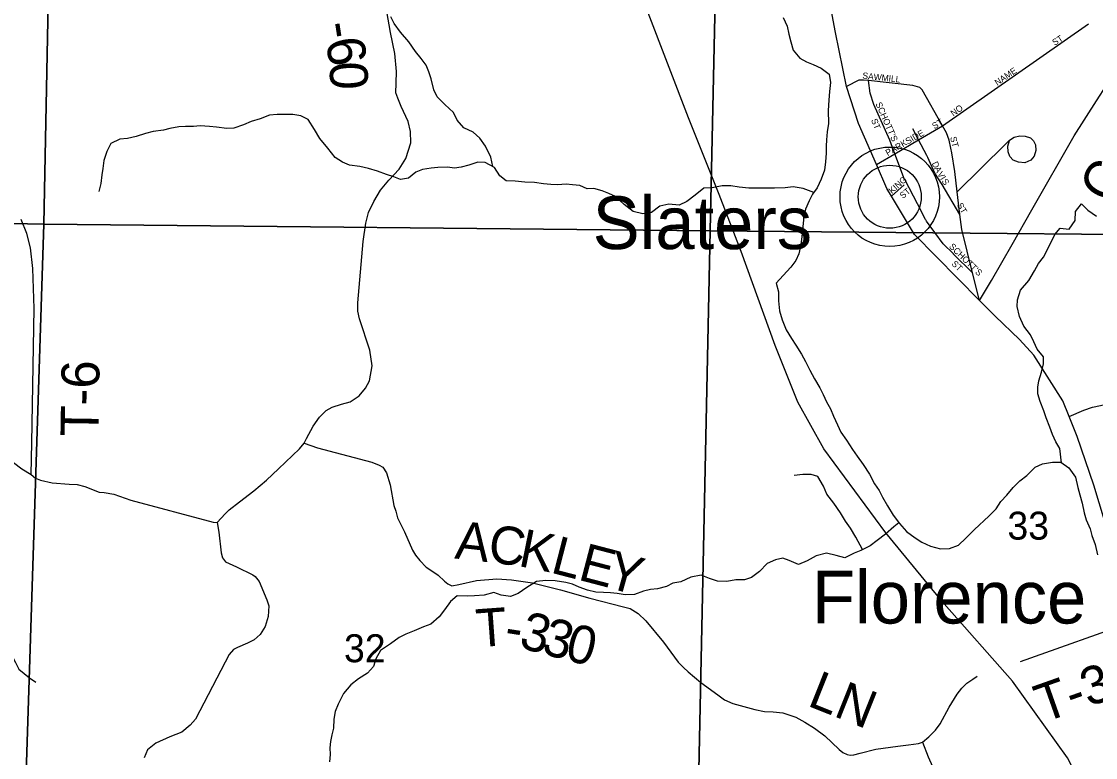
# Model space of a CAD drawing. Extents: x 2043100 to 2470832, y 443715 to 810583.
# Drawn here: x 2231654 to 2240142, y 640063 to 645875 of the extents above; entities that cross this region are included whole.
import ezdxf

# ---------------------------------------------------------------- set-up
doc = ezdxf.new("R2010")
doc.units = 0
for name, color, linetype in [('GM_X_County_Road', 7, 'Continuous'), ('GM_X_County_Road_Text', 7, 'Continuous'), ('GM_X_Interstate_Route', 7, 'Continuous'), ('GM_X_Major_River', 7, 'Continuous'), ('GM_X_Minor_River', 7, 'Continuous'), ('GM_X_Section', 7, 'Continuous'), ('GM_X_Section_Text', 7, 'Continuous'), ('GM_X_State_Route', 7, 'Continuous'), ('GM_X_Township_Road', 7, 'Continuous'), ('GM_X_Township_Road_Text', 7, 'Continuous'), ('GM_X_Township_ROW', 7, 'Continuous'), ('GM_X_Township_Subdivision', 7, 'Continuous'), ('GM_X_Township_Subdivision_Text', 7, 'Continuous'), ('GM_X_Unincorporated', 7, 'Continuous'), ('GM_X_Unincorporated_Location', 7, 'Continuous'), ('GM_X_Unincorporated_Text', 7, 'Continuous')]:
    doc.layers.add(name, color=color, linetype=linetype)

msp = doc.modelspace()

# ---------------------------------------------------------------- linework, layer by layer
at = {"layer": 'GM_X_County_Road'}
for points in [[(2239482.6, 644115.4), (2239637.5, 644388.1), (2239972.9, 644973.3), (2240150.6, 645247.8), (2240230.5, 645374.1), (2240256.4, 645428.2), (2240278.3, 645496.3), (2240298.2, 645656.5), (2240331.8, 646091), (2240373.6, 646383.4), (2240425.3, 646751.9), (2240443.2, 646828), (2240489.1, 646984.3), (2240560.8, 647214.6), (2240640.6, 647429), (2240738.4, 647701.5), (2240782.3, 647767.6), (2240840.2, 647833.7), (2240976.1, 647962.1), (2241048, 648060.3), (2241073.9, 648100.4), (2241083.9, 648122.4)], [(2239224.2, 643672.7), (2239320, 643829), (2239482.6, 644115.4)], [(2231591.4, 642391.7), (2231657.4, 642343.8), (2231731.4, 642297.8), (2231765.5, 642267.8), (2231803.5, 642251.9), (2231895.5, 642232), (2232031.4, 642222.2), (2232093.4, 642218.3), (2232155.4, 642202.4), (2232267.4, 642158.5), (2232307.4, 642154.5), (2232385.4, 642142.7), (2232519.4, 642094.8), (2233169.4, 641921.6), (2233199.4, 641919.7), (2233213.5, 641843.6), (2233233.6, 641679.4), (2233243.6, 641639.4), (2233265.6, 641607.4), (2233353.7, 641569.5), (2233481.7, 641505.6), (2233499.7, 641491.6), (2233531.7, 641451.7), (2233593.8, 641307.6), (2233607.8, 641259.6), (2233603.9, 641175.5), (2233580, 641097.3), (2233540, 641035.2), (2233494.1, 640991.1), (2233440.1, 640965), (2233360.2, 640932.8), (2233330.2, 640916.7), (2233296.2, 640876.6), (2233264.3, 640816.5), (2233028.7, 640365.6), (2232986.8, 640317.5), (2232922.8, 640263.3), (2232826.9, 640227.2), (2232714.9, 640176.9), (2232651, 640122.8), (2232625.1, 640060.7)]]:
    msp.add_lwpolyline(points, dxfattribs=at)
at = {"layer": 'GM_X_Interstate_Route'}
msp.add_lwpolyline([(2240394.7, 638771), (2240382.5, 638881.1), (2240303.2, 639267.5), (2240121.4, 639665.5), (2239921.6, 640061.4), (2239486.5, 640666.7), (2238945.3, 641275.5), (2238484.4, 641836.6), (2237995, 642501.7), (2237789.2, 642869.6), (2237609.2, 643317.8), (2237341.9, 644058.2), (2237167.9, 644510.4), (2236925.2, 645114.6), (2236607.5, 645943), (2236281.8, 646755.3), (2236081.5, 647271.5), (2235837.1, 647771.5), (2235579.2, 648157.2), (2235141.7, 648882.8), (2234805.3, 649336.2), (2234488.5, 649938.1), (2234352.9, 650290.3), (2234278.2, 650792.6)], dxfattribs=at)
at = {"layer": 'GM_X_Major_River'}
for points in [[(2237674.1, 645907.4), (2237704.7, 645839.7), (2237717.4, 645775.8), (2237734, 645713.9), (2237752.7, 645650.1), (2237805.3, 645584.6), (2237857.6, 645557.2), (2237909.8, 645535.7), (2237974.1, 645506.4), (2238036.5, 645459), (2238047.2, 645393.1), (2238039.9, 645323), (2238034.6, 645254.9), (2238029.4, 645172.8), (2238030.5, 645070.7), (2238021.2, 645004.5), (2238015.8, 644940.4), (2238012.3, 644890.4), (2238012.9, 644836.3), (2238007.6, 644768.2), (2238000.3, 644700.1), (2237973, 644629.7), (2237941.7, 644561.3), (2237906.2, 644510.9), (2237878.8, 644458.6), (2237849.5, 644392.2), (2237838.1, 644334.1), (2237832.6, 644283.9), (2237827.2, 644227.9), (2237821.7, 644177.8), (2237812.4, 644111.6), (2237797.1, 644039.4), (2237773.6, 643989.1), (2237734.2, 643934.6), (2237672.9, 643869.9), (2237617.5, 643809.3), (2237636.2, 643739.4), (2237636.9, 643669.4), (2237645.8, 643589.4), (2237666.5, 643519.6), (2237697.3, 643439.9), (2237739.9, 643372.3), (2237772.5, 643320.6), (2237817.2, 643247), (2237849.8, 643189.4), (2237884.5, 643121.7), (2237921.1, 643054), (2237963.9, 642982.4), (2237990.4, 642930.7), (2238017, 642873), (2238047.5, 642817.2), (2238072.1, 642759.5), (2238102.8, 642689.8), (2238129.4, 642632), (2238174, 642568.4), (2238220.8, 642494.9), (2238257.3, 642443.3)], [(2238257.3, 642443.3), (2238305.9, 642375.8), (2238356.7, 642300.2), (2238395.5, 642224.6), (2238432, 642171), (2238458.5, 642119.2), (2238499.2, 642051.6), (2238543.9, 641978), (2238592.6, 641910.5), (2238647.2, 641847.1), (2238717.7, 641797.8), (2238770, 641764.4), (2238838.3, 641731.1), (2238916.5, 641711.9), (2238988.5, 641714.7), (2239058.2, 641739.5), (2239117.6, 641794.2), (2239184.9, 641863), (2239299.8, 641968.3), (2239357.1, 642027), (2239394.5, 642083.4), (2239440, 642135.9), (2239491.4, 642196.5), (2239542.8, 642247.1), (2239598.4, 642289.8), (2239663.7, 642356.5), (2239723.4, 642381.2), (2239801.2, 642396.1), (2239867.2, 642394.8), (2239931.6, 642349.5), (2239984.4, 642278), (2240003.2, 642194.1), (2240017.8, 642136.2), (2240036.5, 642070.4), (2240053.2, 641996.5), (2240067.8, 641940.6), (2240098.5, 641868.9), (2240113, 641815), (2240139.7, 641745.3), (2240158.6, 641663.4)]]:
    msp.add_lwpolyline(points, dxfattribs=at)
at = {"layer": 'GM_X_Minor_River'}
for points in [[(2235378.2, 644729.9), (2235363.1, 644803.1), (2235320.8, 644891), (2235276.7, 644952.9), (2235224.5, 645000.7), (2235150.5, 645036.5), (2235098.3, 645096.4), (2235068.1, 645156.3), (2235000, 645220.1), (2234939.8, 645279.9), (2234913.6, 645335.9), (2234891.4, 645421.9), (2234873.2, 645477.9), (2234853.1, 645529.8), (2234812.9, 645583.7), (2234768.8, 645639.6), (2234716.6, 645715.5), (2234650.4, 645791.3), (2234598.2, 645859.2), (2234572, 645913.2)], [(2237915.7, 644524.3), (2237830.9, 644557.4), (2237752.9, 644569.2), (2237689, 644560.9), (2237605, 644558.6), (2237537, 644560.4), (2237475.1, 644558.2), (2237401.1, 644557.9), (2237327.1, 644567.7), (2237259.1, 644577.4), (2237191.1, 644577.2), (2237113.2, 644562.9), (2237047.2, 644558.7), (2236979.4, 644504.4), (2236911.6, 644454.2), (2236851.7, 644423.9), (2236769.7, 644431.7), (2236699.8, 644417.4), (2236633.9, 644367.1), (2236564, 644356.9), (2236488, 644374.6), (2236417.8, 644430.4), (2236349.7, 644492.2), (2236295.6, 644516.1), (2236243.6, 644537.9), (2236177.5, 644555.7), (2236123.6, 644553.5), (2236067.5, 644581.3), (2236009.5, 644585.2), (2235957.5, 644591), (2235889.6, 644586.7), (2235837.6, 644588.5), (2235779.6, 644594.4), (2235709.6, 644604.1), (2235631.6, 644607.9), (2235555.6, 644615.6), (2235485.6, 644617.4), (2235435.5, 644657.2), (2235391.3, 644723.1), (2235319.2, 644760.9), (2235261.2, 644764.7), (2235189.3, 644740.4), (2235129.4, 644726.2), (2235075.4, 644716), (2235021.4, 644723.8), (2234945.5, 644723.6), (2234891.5, 644717.4), (2234823.6, 644707.1), (2234769.6, 644684.9), (2234711.8, 644638.7), (2234649.9, 644628.5), (2234595.8, 644648.3), (2234537.8, 644666.1), (2234467.7, 644693.9), (2234397.7, 644713.6), (2234327.7, 644729.4), (2234247.6, 644741.2), (2234191.6, 644765), (2234133.5, 644800.8), (2234075.3, 644874.6), (2234013.1, 644952.5), (2233970.9, 645022.4), (2233918.7, 645102.3), (2233862.6, 645130.1), (2233798.6, 645139.9), (2233732.6, 645141.6), (2233674.6, 645141.4), (2233614.7, 645135.2), (2233540.8, 645106.9), (2233468.9, 645084.7), (2233409, 645058.4), (2233333.1, 645034.2), (2233277.1, 645030), (2233195.1, 645039.7), (2233139.1, 645047.5), (2233065.1, 645051.2), (2233013.1, 645047), (2232951.1, 645046.8), (2232897.2, 645044.6), (2232827.2, 645030.4), (2232775.3, 645016.2), (2232695.3, 645005.9), (2232633.4, 644989.7), (2232559.5, 644967.4), (2232491.6, 644951.1), (2232431.6, 644944.9), (2232361.7, 644912.7), (2232329.9, 644848.5), (2232306.1, 644778.4), (2232298.3, 644714.3), (2232290.5, 644664.2), (2232280.7, 644596.1), (2232264.9, 644532)], [(2239873.3, 642390.5), (2239860.3, 642502.9), (2239828.1, 642556.8), (2239802, 642612.8), (2239779.8, 642670.7), (2239751.6, 642746.7), (2239733.4, 642800.7), (2239705.2, 642874.6), (2239687.1, 642934.6), (2239684.9, 642988.6), (2239692.7, 643038.7), (2239714.5, 643104.8), (2239730.3, 643170.9), (2239730.2, 643227), (2239682, 643288.8), (2239653.8, 643346.8), (2239627.7, 643400.7), (2239575.5, 643470.6), (2239541.3, 643544.6), (2239523.1, 643624.5), (2239524.9, 643678.6), (2239548.7, 643752.7), (2239614.4, 643831), (2239660.2, 643905.2), (2239692, 643963.4), (2239729.8, 644013.5), (2239757.6, 644063.7), (2239821.2, 644192), (2239863.1, 644242.2), (2239933.1, 644236.4), (2239980.8, 644304.6), (2239982.6, 644374.7), (2240030.4, 644434.9), (2240080.6, 644385), (2240148.7, 644339.2)], [(2238300, 641705.1), (2238249, 641802.8), (2238206.8, 641874.7), (2238166.7, 641928.7), (2238126.5, 641994.6), (2238074.3, 642070.4), (2238018.1, 642142.3), (2237991.9, 642206.2), (2237947.7, 642282.2), (2237895.7, 642298), (2237827.7, 642297.8), (2237759.7, 642289.5)], [(2238588.2, 641916.7), (2238548.7, 641883.9), (2238482.8, 641827.7), (2238417, 641777.4), (2238361.2, 641735.2), (2238287.3, 641698.9), (2238235.4, 641676.7), (2238161.5, 641640.4), (2238091.5, 641658.2), (2238015.5, 641675.9), (2237933.6, 641655.6), (2237863.7, 641615.4), (2237793.8, 641587.1), (2237721.8, 641618.9), (2237669.7, 641636.7), (2237611.8, 641624.5), (2237545.9, 641594.3), (2237486.1, 641532), (2237422.3, 641485.8), (2237368.4, 641465.5), (2237298.4, 641465.3), (2237228.4, 641453.1), (2237154.5, 641454.8), (2237092.4, 641476.6), (2237026.4, 641502.4), (2236944.4, 641488.1), (2236864.6, 641449.8), (2236802.6, 641439.6), (2236750.7, 641413.4), (2236680.8, 641395.1), (2236624.9, 641388.9), (2236570.9, 641376.7), (2236499, 641350.5), (2236425.1, 641348.2), (2236363, 641358), (2236309.1, 641363.8), (2236253.1, 641365.6), (2236193.1, 641369.4), (2236127.1, 641385.2), (2236061, 641407), (2236009, 641432.8), (2235956.9, 641444.7), (2235870.9, 641458.4), (2235797, 641460.1), (2235725, 641453.8), (2235647.2, 641405.5), (2235579.3, 641359.3), (2235519.4, 641335.1), (2235445.4, 641344.8), (2235387.4, 641366.6), (2235309.5, 641344.3), (2235233.5, 641340.1), (2235175.5, 641337.9), (2235097.6, 641339.6), (2235043.7, 641295.4), (2234995.9, 641229.2), (2234954.1, 641173), (2234888.3, 641116.7), (2234830.4, 641094.5), (2234758.5, 641062.2), (2234690.6, 641035.9), (2234638.7, 641011.7), (2234570.9, 640961.5), (2234491, 640909.2), (2234453.3, 640841), (2234437.4, 640782.9), (2234387.6, 640728.7), (2234317.8, 640684.4), (2234255.9, 640636.1), (2234200.2, 640567.9), (2234156.4, 640483.7), (2234132.6, 640427.5), (2234122.8, 640365.5), (2234119, 640293.4), (2234107.2, 640243.3), (2234095.3, 640189.2), (2234091.5, 640139.2), (2234093.6, 640087.2), (2234087.8, 640029.1)], [(2231165.5, 641778.1), (2231187.7, 641710.1), (2231209.9, 641636.1), (2231220, 641586.1), (2231224.2, 641536.1), (2231218.4, 641476), (2231204.5, 641415.9), (2231196.7, 641361.9), (2231186.9, 641307.8), (2231191.1, 641245.8), (2231221.2, 641189.8), (2231297.4, 641124), (2231349.5, 641094.2), (2231409.6, 641052.4), (2231451.7, 640998.5), (2231529.9, 640930.7), (2231576, 640874.8), (2231606.2, 640812.9), (2231634.4, 640761), (2231716.5, 640691.2), (2231768.6, 640657.4)]]:
    msp.add_lwpolyline(points, dxfattribs=at)
at = {"layer": 'GM_X_Section'}
for points in [[(2226378.6, 649710.8), (2231937.4, 649640.6), (2231831, 644275.3), (2226281.7, 644387.8), (2226283.1, 644449.8)], [(2231937.4, 649640.6), (2237212.3, 649559.4), (2237095.6, 644222), (2231831, 644275.3)], [(2237212.3, 649559.4), (2242487.2, 649484.1), (2242378.2, 644174.8), (2237095.6, 644222)], [(2231831, 644275.3), (2231663.3, 639041.5), (2231545.3, 639036.3), (2226228.4, 639113.1), (2226281.7, 644387.8)], [(2237095.6, 644222), (2236986.2, 638960.8), (2236824, 638967.1), (2231663.3, 639041.5), (2231831, 644275.3)], [(2242378.2, 644174.8), (2242269, 638887.7), (2242088.5, 638885.8), (2236986.2, 638960.8), (2237095.6, 644222)]]:
    msp.add_lwpolyline(points, close=True, dxfattribs=at)
at = {"layer": 'GM_X_State_Route'}
msp.add_lwpolyline([(2240384.2, 641385), (2240367.1, 641432.7), (2240278.9, 641720.1), (2240265.4, 641764.1), (2240255.7, 641796.2), (2240129.1, 642214.4), (2239996.8, 642598.6), (2239934.5, 642755.4), (2239884.6, 642880.8), (2239654.4, 643240.8), (2239542.3, 643362.8), (2239348.2, 643548.7), (2239224.2, 643672.7), (2238711.9, 644192.5), (2238530.6, 644495.1), (2238493.7, 644556.6), (2238411.1, 644745.2), (2238269.4, 645068.8), (2238174.6, 645363.4), (2238086.8, 645787.4), (2237986.4, 646321.9), (2237949.9, 646434.6), (2237924.3, 646608.8)], dxfattribs=at)
at = {"layer": 'GM_X_Township_Road'}
for points in [[(2233199.4, 641919.7), (2233263.1, 641988.2), (2233294.8, 642018.5), (2233376.4, 642083.2), (2233489.7, 642170.2), (2233591.1, 642253.1), (2233686.4, 642342), (2233851.2, 642501.5), (2233888.9, 642545.9), (2233906.6, 642582), (2233960, 642678.6), (2234009.4, 642751.1), (2234063, 642803.6), (2234110.8, 642830), (2234182.6, 642852.6), (2234250.5, 642873.1), (2234322.1, 642919.7), (2234371.7, 642980.2), (2234403.3, 643036.5), (2234426.4, 643156.9), (2234407.5, 643280.9), (2234325.8, 643528.5), (2234313.4, 643588.5), (2234312.9, 643654.6), (2234353.5, 644137.5), (2234376.5, 644281.9), (2234397.9, 644368.2), (2234439.2, 644452.6), (2234490.6, 644543.1), (2234558, 644621.8), (2234639.4, 644708.5), (2234692.7, 644793), (2234729.9, 644917.5), (2234729.2, 645007.6), (2234710.7, 645085.5), (2234655.9, 645205.3), (2234627.4, 645269.1), (2234613.1, 645313.1), (2234614.6, 645387.2), (2234617.9, 645479.3), (2234604.9, 645623.4), (2234569.8, 645789.3), (2234542.6, 645955.3)], [(2239430.5, 644907.4), (2239461.1, 644937.5), (2239499.7, 644961.2), (2239545, 644972.6), (2239585.2, 644970), (2239627, 644956.7), (2239652, 644933.3), (2239667, 644900.7), (2239669.4, 644855.8), (2239656.4, 644812.4), (2239629.5, 644781), (2239582.2, 644758.1), (2239532.3, 644763.3), (2239490.8, 644780.3), (2239465.6, 644810.2), (2239451.2, 644847), (2239449.6, 644889.8), (2239461.1, 644936.5)], [(2239047.5, 644531.4), (2239430.5, 644907.4)], [(2231731.4, 642297.8), (2231737.2, 642548.1), (2231754.4, 643609.4), (2231744.1, 643925.7), (2231726, 644087.9), (2231697.9, 644199.9), (2231651.8, 644312)], [(2233888.9, 642545.9), (2233993.1, 642508.6), (2234423.8, 642395.9), (2234481.9, 642372.3), (2234510, 642356.5), (2234538.3, 642310.7), (2234569, 642216.8), (2234598.1, 642052.8), (2234612.4, 642008.9), (2234626.8, 641956.9), (2234681.6, 641845.2), (2234744.6, 641701.5), (2234766.8, 641661.7), (2234801.1, 641617.9), (2234853.5, 641566.2), (2234903.7, 641532.6), (2234945.9, 641502.9), (2234998.2, 641455.2), (2235022.3, 641433.4), (2235056.4, 641419.6), (2235110.3, 641428.1), (2235250, 641461.2), (2235409.9, 641474.5), (2235525.9, 641467.4), (2235692, 641442.6), (2235914.3, 641386.3), (2236144.7, 641320), (2236413, 641254.1), (2236465.1, 641238.5), (2236527.4, 641200.9), (2236587.8, 641143.3), (2236726.9, 640974.2), (2236844, 640816.9), (2236886.2, 640773.2), (2236922.5, 640739.4), (2237023, 640656.1), (2237157.7, 640557), (2237209.9, 640519.4), (2237276.1, 640489.9), (2237450.4, 640441.2), (2237526.4, 640425.8), (2237594.4, 640424.3), (2237670.4, 640416.9), (2237772.6, 640381.6), (2237844.9, 640342.1), (2237921.2, 640294.7), (2238003.6, 640235.3), (2238116.3, 640126), (2238144.4, 640102.2), (2238180.5, 640086.5), (2238202.5, 640082.3), (2238233.1, 640084.2), (2238282.4, 640097.3), (2238406.1, 640128.3), (2238579.9, 640151.7), (2238664.6, 640162.7), (2238743.7, 640173), (2238775.6, 640185.2), (2238820.4, 640067.4), (2238897.6, 639891.8)], [(2239548.4, 640822), (2240468.9, 641148.8)]]:
    msp.add_lwpolyline(points, dxfattribs=at)
at = {"layer": 'GM_X_Township_ROW'}
msp.add_lwpolyline([(2239020.2, 644037.9), (2239018.5, 644039.6), (2238937.9, 644118.8), (2238805.8, 644298.8), (2238800, 644309.9)], dxfattribs=at)
at = {"layer": 'GM_X_Township_Subdivision'}
for points in [[(2238932.7, 645050.7), (2240085.1, 645857.2)], [(2239224.2, 643672.7), (2239170.5, 643890.2), (2239085.8, 644233.1), (2239070.5, 644352.1), (2239047.5, 644531.4), (2239031.4, 644691.6), (2239005.7, 644838.9), (2238999.3, 644875.7), (2238985.9, 644939.1), (2238965.2, 644995.8), (2238932.7, 645050.7), (2238771, 645335.9), (2238753, 645353.9), (2238699, 645369.8), (2238346.6, 645408.9), (2238307.1, 645413.3), (2238271.1, 645411.2), (2238174.6, 645363.4)], [(2238735.1, 644434.4), (2238636.9, 644622.7), (2238633.6, 644628.9), (2238556.3, 644830.3), (2238515.4, 644937.1), (2238389.2, 645221.2), (2238361.1, 645309.3), (2238346.6, 645408.9)], [(2238411.1, 644745.2), (2238556.3, 644830.3), (2238743.7, 644940), (2238932.7, 645050.7)], [(2238808.8, 644817.5), (2238743.7, 644940), (2238697.3, 645027.4)], [(2239070.5, 644352.1), (2238930, 644588.1), (2238872.8, 644676.7), (2238817.4, 644801.4), (2238808.8, 644817.5)], [(2238530.6, 644495.1), (2238629.6, 644584.8)], [(2238800, 644309.9), (2238799.3, 644311.2), (2238735.1, 644434.4)], [(2239170.5, 643890.2), (2239020.2, 644037.9)], [(2239934.5, 642755.4), (2240048.6, 642804.9), (2240118.6, 642829.1), (2240180.5, 642843.2), (2240193, 642845.1), (2240274.5, 642857.3), (2240404.5, 642859.4), (2240582.4, 642851.9), (2240628.4, 642849.8), (2240757.2, 642845.9), (2240814.3, 642844.1), (2240879.1, 642845)], [(2238775.6, 640185.2), (2238825.3, 640225.7), (2238876.9, 640278.1), (2238914.5, 640328.5), (2238985.6, 640459.2), (2239048.8, 640563.8), (2239084.5, 640610.2), (2239126.2, 640650.6), (2239171.9, 640681), (2239207.7, 640705.3)]]:
    msp.add_lwpolyline(points, dxfattribs=at)
at = {"layer": 'GM_X_Unincorporated'}
for radius in [392.8, 249]:
    msp.add_circle((2238516, 644491.3), radius, dxfattribs=at)
at = {"layer": 'GM_X_Unincorporated_Location'}
msp.add_line((2238516, 644491.3), (2238516, 644491.3), dxfattribs=at)

# ---------------------------------------------------------------- texts
at = {"layer": 'GM_X_County_Road_Text'}
msp.add_text('C', height=300, rotation=59.92252, dxfattribs=at).set_placement((2240258.2, 644420.9))
at = {"layer": 'GM_X_Section_Text'}
for s, p in [('33', (2239445.8, 641783.5)), ('32', (2234203.2, 640815.4))]:
    msp.add_text(s, height=220.83, rotation=0.00001, dxfattribs=at).set_placement(p)
at = {"layer": 'GM_X_Township_Road_Text'}
for s, rotation, p in [('-', 278.87954, (2234033.2, 645857)), ('6', 281.00653, (2234054.3, 645723.3)), ('0', 271.82178, (2234088.2, 645554.5)), ('T-6', 89.04566, (2232262, 642595.6)), ('A', 353.53511, (2235071.9, 641635.5)), ('C', 353.09042, (2235333.6, 641605.8)), ('K', 348.46218, (2235571.9, 641577.2)), ('L', 345.47108, (2235826.5, 641525.3)), ('E', 345.34631, (2236043.6, 641469.1)), ('Y', 344.38736, (2236259.4, 641412.6)), ('T', 4.13477, (2235255.9, 640933.3)), ('3', 345.40211, (2235575.8, 640932.9)), ('3', 344.80376, (2235753.8, 640886.6)), ('-', 351.16778, (2235461.8, 640950.2)), ('0', 345.95048, (2235938.5, 640836.5)), ('T-330A', 19.46432, (2239729.5, 640335.2)), ('LN', 338.29451, (2237855.7, 640475.3))]:
    msp.add_text(s, height=300, rotation=rotation, dxfattribs=at).set_placement(p)
at = {"layer": 'GM_X_Township_Subdivision_Text'}
for s, rotation, p in [('ST', 32.73207, (2239819.5, 645682.9)), ('NAME', 34.62365, (2239366, 645365.9)), ('SAWMILL', 353.85629, (2238298, 645424.6)), ("SCHOTT'S", 293.78214, (2238402.2, 645225.8)), ('NO', 35.22264, (2239018.3, 645123.9)), ('ST', 291.7989, (2238367.1, 645097.1)), ('ST', 31.60468, (2238869.2, 645023)), ('PARKSIDE', 29.95058, (2238499.8, 644811.9)), ('ST', 284.02982, (2238992.3, 644960.4)), ('D', 295.85146, (2238846.6, 644755.1)), ('A', 296.76642, (2238866.2, 644714.7)), ('KING', 41.49864, (2238533.6, 644511.7)), ('V', 301.72221, (2238888.3, 644671.3)), ('I', 302.50359, (2238911.8, 644633.2)), ('S', 302.47749, (2238923.7, 644614.7)), ('ST', 39.80915, (2238619.3, 644472.6)), ('ST', 299.75497, (2239044.2, 644425.8)), ("SCHOTT'S", 315.62923, (2238981.1, 644093.4)), ('ST', 315.00994, (2239000, 643958.1))]:
    msp.add_text(s, height=50, rotation=rotation, dxfattribs=at).set_placement(p)
at = {"layer": 'GM_X_Unincorporated_Text'}
for s, p in [('Slaters', (2236167.8, 644078.1)), ('Florence', (2237901.4, 641121.3))]:
    msp.add_text(s, height=416.67, rotation=0.00001, dxfattribs=at).set_placement(p)

doc.saveas('drawing.dxf')
